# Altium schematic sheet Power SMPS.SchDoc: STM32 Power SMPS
size A3; Date: Not used; ApprovedBy: Not used; CheckedBy: Not used; Author: Not used; CompanyName: STMicroelectronics; DrawnBy: Not used; Engineer: Not used; Organization: Not used; Address1: Not used; Address2: Not used; Address3: Not used; Address4: Not used; DocumentNumber: 7; Revision: Not used; SheetNumber: 7; SheetTotal: 8
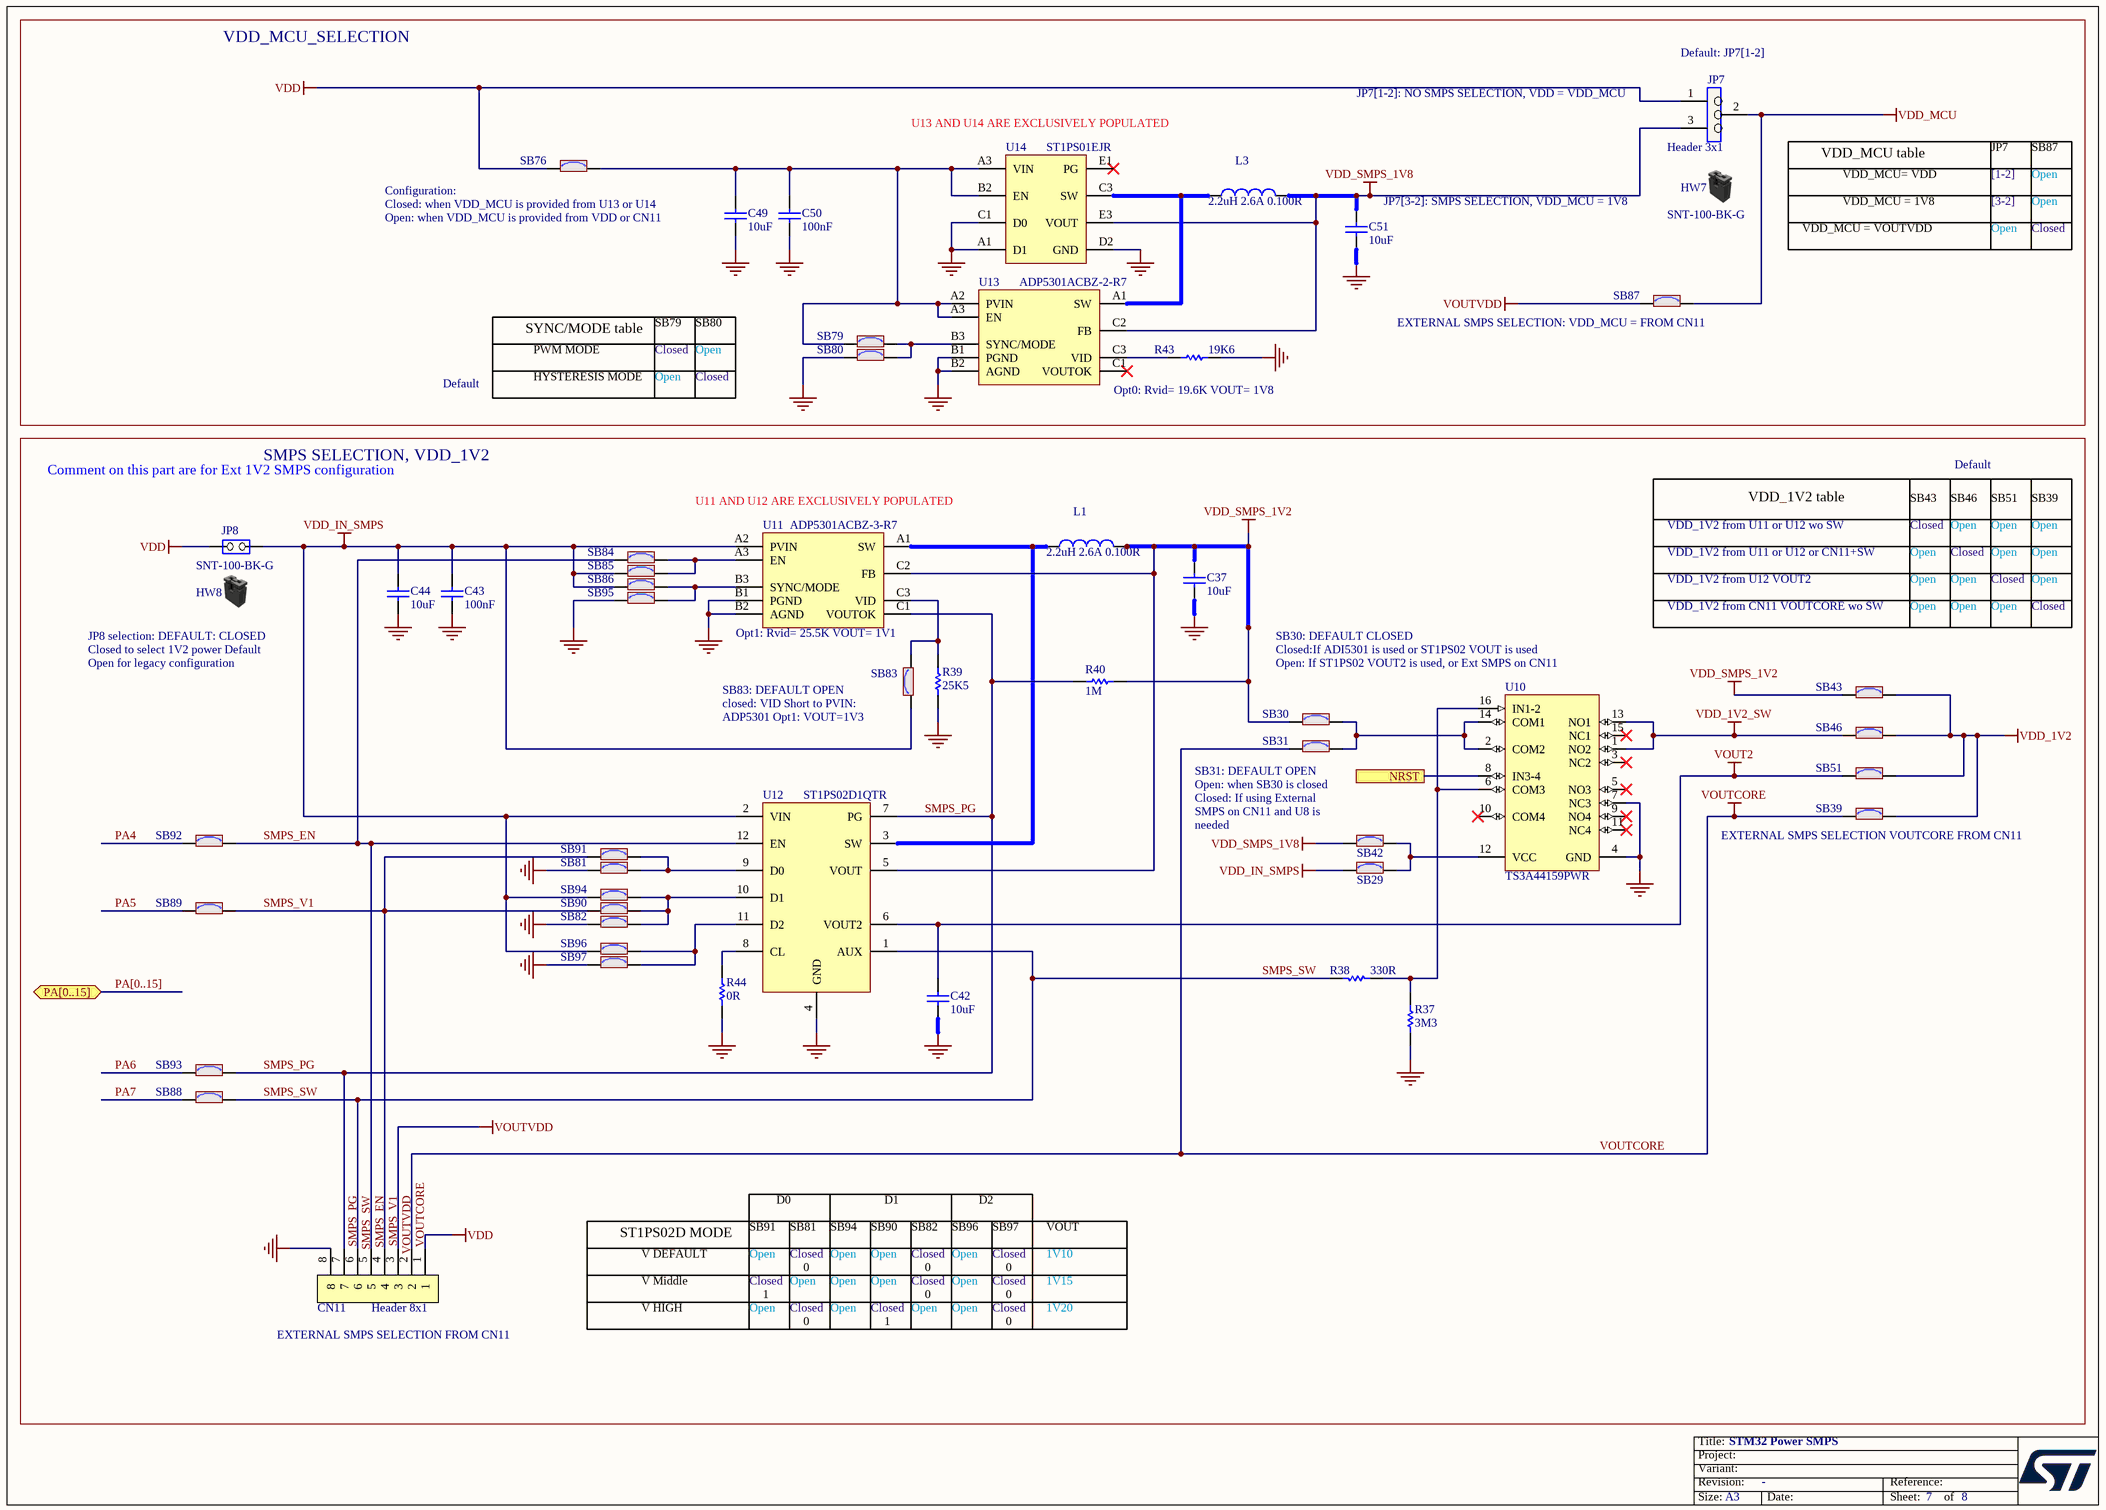
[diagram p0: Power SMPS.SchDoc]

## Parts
C37  value 10uF  [C0603]  (hidden comment: Capacitor)
C42  value 10uF  [C0603]  (hidden comment: Capacitor)
C43  value 100nF  [C0402]  (hidden comment: Capacitor)
C44  value 10uF  [C0603]  (hidden comment: Capacitor)
C49  value 10uF  [C0603]  (hidden comment: Capacitor)
C50  value 100nF  [C0603]  (hidden comment: Capacitor)
C51  value 10uF  [C0603]  (hidden comment: Capacitor)
CN11  Header 8x1  [CON_SAMTEC_TSW-108-07-X-S]
HW7  value SNT-100-BK-G  (hidden comment: Shunt Black 2.54mm)  (mechanical)
HW8  value SNT-100-BK-G  (hidden comment: Shunt Black 2.54mm)  (mechanical)
JP7  value Header 3x1  [CON_SAMTEC_TSW-103-07-F-S]  (hidden comment: Jumper_Header 3x1)
JP8  Jumper_Header 2x1  [CON_SAMTEC_TSW-102-07-G-S]  (value not drawn)
L1  value 2.2uH 2.6A 0.100R  [IND_TDK_VLS252010HBX-1]  (hidden comment: Inductor)
L3  value 2.2uH 2.6A 0.100R  [IND_TDK_VLS252010HBX-1]  (hidden comment: Inductor)
R37  value 3M3  [R0603]  (hidden comment: Resistor)
R38  value 330R  [R0603]  (hidden comment: Resistor)
R39  value 25K5  [R0603]  (hidden comment: Resistor)
R40  value 1M  [R0603]  (hidden comment: Resistor)
R43  value 19K6  [R0603]  (hidden comment: Resistor)
R44  value 0R  [R0603]  (hidden comment: Resistor)
SB29  SB_ON  [SOLDER-BRIDGE_R0603-0R]  (value not drawn)
SB30  SB_ON  [SOLDER-BRIDGE_R0603-0R]  (value not drawn)
SB31  SB_ON  [SOLDER-BRIDGE_R0603-0R]  (value not drawn)
SB39  SB_ON  [SOLDER-BRIDGE_R0603-0R]  (value not drawn)
SB42  SB_ON  [SOLDER-BRIDGE_R0603-0R]  (value not drawn)
SB43  SB_ON  [SOLDER-BRIDGE_R0603-0R]  (value not drawn)
SB46  SB_ON  [SOLDER-BRIDGE_R0603-0R]  (value not drawn)
SB51  SB_ON  [SOLDER-BRIDGE_R0603-0R]  (value not drawn)
SB76  SB_ON  [SOLDER-BRIDGE_R0603-0R]  (value not drawn)
SB79  SB_ON  [SOLDER-BRIDGE_R0603-0R]  (value not drawn)
SB80  SB_ON  [SOLDER-BRIDGE_R0603-0R]  (value not drawn)
SB81  SB_ON  [SOLDER-BRIDGE_R0603-0R]  (value not drawn)
SB82  SB_ON  [SOLDER-BRIDGE_R0603-0R]  (value not drawn)
SB83  SB_ON  [SOLDER-BRIDGE_R0603-0R]  (value not drawn)
SB84  SB_ON  [SOLDER-BRIDGE_R0603-0R]  (value not drawn)
SB85  SB_ON  [SOLDER-BRIDGE_R0603-0R]  (value not drawn)
SB86  SB_ON  [SOLDER-BRIDGE_R0603-0R]  (value not drawn)
SB87  SB_ON  [SOLDER-BRIDGE_R0603-0R]  (value not drawn)
SB88  SB_ON  [SOLDER-BRIDGE_R0603-0R]  (value not drawn)
SB89  SB_ON  [SOLDER-BRIDGE_R0603-0R]  (value not drawn)
SB90  SB_ON  [SOLDER-BRIDGE_R0603-0R]  (value not drawn)
SB91  SB_ON  [SOLDER-BRIDGE_R0603-0R]  (value not drawn)
SB92  SB_ON  [SOLDER-BRIDGE_R0603-0R]  (value not drawn)
SB93  SB_ON  [SOLDER-BRIDGE_R0603-0R]  (value not drawn)
SB94  SB_ON  [SOLDER-BRIDGE_R0603-0R]  (value not drawn)
SB95  SB_ON  [SOLDER-BRIDGE_R0603-0R]  (value not drawn)
SB96  SB_ON  [SOLDER-BRIDGE_R0603-0R]  (value not drawn)
SB97  SB_ON  [SOLDER-BRIDGE_R0603-0R]  (value not drawn)
U10  TS3A44159PWR  [ICC_TSSOP16_5P1X4P5_P065]
U11  value ADP5301ACBZ-3-R7  [ICC_WLCSP9_1P65X1P87_P050]  (hidden comment: ADP5301)
U12  ST1PS02D1QTR  [ICC_TQFN12_2X1P7_P040]
U13  value ADP5301ACBZ-2-R7  [ICC_WLCSP9_1P65X1P87_P050]  (hidden comment: ADP5301)
U14  ST1PS01EJR  [ICC_FLIP-CHIP-BGA8_1P11X1P41_P040]

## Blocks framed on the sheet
VDD_MCU_SELECTION: C49-C51 HW7 JP7 L3 R43 SB76 SB79 SB80 SB87 U13 U14
SMPS SELECTION, VDD_1V2: C37 C42-C44 CN11 HW8 JP8 L1 R37-R40 R44 SB29-SB31 SB39 SB42 SB43 SB46 SB51 SB81-SB86 SB88-SB97 U10-U12

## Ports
NRST, PA[0..15] (bidir)

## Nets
GND: C37.1 C42.1 C43.1 C44.1 C49.1 C50.1 C51.1 CN11.8 R37.1 R39.1 R43.2 R44.1 SB80.1 SB81.1 SB82.1 SB95.1 SB97.1 U10.4(GND) U10.7(NC3) U11.B1(PGND) U11.B2(AGND) U12.4(GND) U13.B1(PGND) U13.B2(AGND) U14.A1(D1) U14.C1(D0) U14.D2(GND)
VDD: CN11.1 JP7.1 JP8.1(COMMON) SB76.1
VDD_1V2: SB39.2 SB43.2 SB46.2 SB51.2
VDD_1V2_SW: SB46.1 U10.1(NO2) U10.13(NO1)
VDD_IN_SMPS: C43.2 C44.2 JP8.2(NO) SB29.1 SB83.1 SB85.1 SB86.1 SB94.1 SB96.1 U11.A2(PVIN) U12.2(VIN)
VDD_MCU: JP7.2 SB87.2
VDD_SMPS_1V2: C37.2 L1.2 R40.2 SB30.1 SB43.1 U11.C2(FB) U12.5(VOUT)
VDD_SMPS_1V8: C51.2 JP7.3 L3.2 SB42.1 U13.C2(FB) U14.E3(VOUT)
VOUT2: C42.2 SB51.1 U12.6(VOUT2)
VOUTCORE: CN11.2 SB31.1 SB39.1
VOUTVDD: CN11.3 SB87.1
NRST: U10.8(IN3-4) ; port NRST
PA4: SB92.2
PA5: SB89.2
PA6: SB93.2
PA7: SB88.2
SMPS_EN: CN11.5 SB84.1 SB92.1 U12.12(EN)
SMPS_PG: CN11.7 R40.1 SB93.1 U11.C1(VOUTOK) U12.7(PG)
SMPS_SW: CN11.6 R38.2 SB88.1 U12.1(AUX)
SMPS_V1: CN11.4 SB89.1 SB90.1 SB91.1
NetC49_2: C49.2 C50.2 SB76.2 SB79.1 U13.A2(PVIN) U13.A3(EN) U14.A3(VIN) U14.B2(EN)
NetL1_1: L1.1 U11.A1(SW) U12.3(SW)
NetL3_1: L3.1 U13.A1(SW) U14.C3(SW)
NetR37_2: R37.2 R38.1 U10.6(COM3) U10.16(IN1-2)
NetR39_2: R39.2 SB83.2 U11.C3(VID)
NetR43_1: R43.1 U13.C3(VID)
NetR44_2: R44.2 U12.8(CL)
NetSB29_2: SB29.2 SB42.2 U10.12(VCC)
NetSB30_2: SB30.2 SB31.2 U10.2(COM2) U10.14(COM1)
NetSB79_2: SB79.2 SB80.2 U13.B3(SYNC/MODE)
NetSB81_2: SB81.2 SB91.2 U12.9(D0)
NetSB82_2: SB82.2 SB90.2 SB94.2 U12.10(D1)
NetSB84_2: SB84.2 SB85.2 U11.A3(EN)
NetSB86_2: SB86.2 SB95.2 U11.B3(SYNC/MODE)
NetSB96_2: SB96.2 SB97.2 U12.11(D2)

Not connected (* = marked no-connect by the designer): U10 3(NC2)* 5(NO3)* 9(NO4)* 10(COM4)* 11(NC4)* 15(NC1)*; U13 C1(VOUTOK)*; U14 E1(PG)*

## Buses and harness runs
bus PA[0..15] = port PA[0..15]

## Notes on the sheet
- JP7[1-2]: NO SMPS SELECTION, VDD = VDD_MCU
- (near JP7) Default: JP7[1-2]
- (near U14) U13 AND U14 ARE EXCLUSIVELY POPULATED
- VDD_MCU table
- VDD_MCU= VDD
- JP7
- [1-2]
- SB87
- Open
- (near SB76) Configuration:
  Closed: when VDD_MCU is provided from U13 or U14
  Open: when VDD_MCU is provided from VDD or CN11
- (near C51) JP7[3-2]: SMPS SELECTION, VDD_MCU = 1V8
- VDD_MCU = VOUTVDD
- VDD_MCU = 1V8
- [3-2]
- Closed
- SYNC/MODE table
- PWM MODE
- HYSTERESIS MODE
- SB79
- SB80
- (near SB87) EXTERNAL SMPS SELECTION: VDD_MCU = FROM CN11
- Default
- Opt0: Rvid= 19.6K VOUT= 1V8
- Comment on this part are for Ext 1V2 SMPS configuration
- (near U11) U11 AND U12 ARE EXCLUSIVELY POPULATED
- VDD_1V2 table
- SB43
- SB46
- SB51
- SB39
- VDD_1V2 from U11 or U12 wo SW
- VDD_1V2 from U11 or U12 or CN11+SW
- VDD_1V2 from U12 VOUT2
- (near U11) Opt1: Rvid= 25.5K VOUT= 1V1
- VDD_1V2 from CN11 VOUTCORE wo SW
- JP8 selection: DEFAULT: CLOSED
  Closed to select 1V2 power Default
  Open for legacy configuration
- (near SB83) SB83: DEFAULT OPEN
  closed: VID Short to PVIN:
  ADP5301 Opt1: VOUT=1V3
- SB30: DEFAULT CLOSED
  Closed:If ADI5301 is used or ST1PS02 VOUT is used
  Open: If ST1PS02 VOUT2 is used, or Ext SMPS on CN11
- SB31: DEFAULT OPEN
  Open: when SB30 is closed
  Closed: If using External SMPS on CN11 and U8 is needed
- (near SB39) EXTERNAL SMPS SELECTION VOUTCORE FROM CN11
- ST1PS02D MODE
- V DEFAULT
- SB91
- D0
- SB81
- SB94
- SB90
- D1
- SB82
- SB96
- D2
- SB97
- VOUT
- 1V10
- V Middle
- V HIGH
- 1
- 0
- 1V15
- 1V20
- EXTERNAL SMPS SELECTION FROM CN11

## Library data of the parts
C37 C42 C44 C49 C51 = MCD-00243: Capacitor, MLCC, 10uF, 6V3, X5R, +/-10%, 0603, T=0,8mm; Manufacturer_Part_Number: CC0603KRX5R5BB106; Manufacturer: YAGEO; Part_Preference: Recommended
C43 = MCD-00006: Capacitor, MLCC, 100nF, 16V, X7R, +/-10%, 0402, T=0.5mm; Manufacturer_Part_Number: CC0402KRX7R7BB104; Manufacturer: YAGEO; Part_Preference: Recommended; Alternate_Manufacturer: MURATA; Alternate_Manufacturer_Part_Number: GCM155R71C104KA55D; Order_Code_RS: 616-9701
C50 = MCD-00237: Capacitor, MLCC, 100nF, 6V3, X5R, +/-10%, 0603, T=0.8mm; Part_Preference: Not recommended; Manufacturer: YAGEO; Manufacturer_Part_Number: CC0603KRX5R5BB104; Component_Country_Of_Origin: China; ShowFields: YES; ID: 2631
CN11 = MCD-00239: Header, 8x1, 2,54mm, VR, TH, Height 5.84mm/2.54mm; Manufacturer_Part_Number: TSW-108-07-G-S; Manufacturer: SAMTEC; Part_Type: Connector; Part_Preference: Recommended
HW7 HW8 = MCD-00043: SHUNT 2.54mm BLACK; Manufacturer: SAMTEC; Part_Type: Misc; Part_Preference: Recommended; Alternate_Manufacturer: JIUBABA; Alternate_Manufacturer_Part_Number: 316102S111A
JP7 = MCD-00111: Header, 3x1, 2,54mm, VR, TH, Height 5.84mm/2.54mm; Manufacturer_Part_Number: TSW-103-07-F-S; Manufacturer: SAMTEC; Part_Type: Connector; Part_Preference: Recommended; Alternate_Manufacturer: FCI; Alternate_Manufacturer_Part_Number: 77311-118-03LF
JP8 = MCD-00045: Header, 2x1, 2,54mm, VR, TH, Height 5.84mm/2.54mm; Manufacturer_Part_Number: TSW-102-07-G-S; Manufacturer: SAMTEC; Part_Type: Connector; Part_Preference: Recommended; Alternate_Manufacturer: JIUBABA; LIANYI; Alternate_Manufacturer_Part_Number: 313102S111116;313102S111116; Value: Shunt not fitted
L1 L3 = MCD-00240: FIXED IND 2.2UH 2.6A 100 mOHM 20% SMD; Manufacturer_Part_Number: VLS252010HBX-2R2M-1; Manufacturer: TDK; Part_Preference: Recommended
R37 = MCD-00241: Resistor,3M3,0603,1%,1/10W; Manufacturer_Part_Number: RC0603FR-073M3L; Manufacturer: YAGEO; BMS_Part_Number: 9129788; Part_Preference: Recommended; Order_Code_RS: 504-6540
R38 = MCD-00197: Resistor,330R,0603,1%,1/10W; Manufacturer_Part_Number: RC0603FR-07330RL; Manufacturer: YAGEO; BMS_Part_Number: 9129729; Part_Preference: Recommended
R39 = MCD-00546: Resistor,25K5,0603,1%,1/10W; Manufacturer_Part_Number: RC0603FR-0725K5L; Manufacturer: YAGEO; Part_Preference: Recommended
R40 = MCD-00257: Resistor,1M,0603,1%,1/10W; Manufacturer_Part_Number: RC0603FR-071ML; Manufacturer: YAGEO; Part_Preference: Recommended
R43 = MCD-00242: Resistor,19K6,0603,1%,1/10W; Manufacturer_Part_Number: RC0603FR-0719K6L; Manufacturer: YAGEO; Part_Preference: Recommended
R44 = MCD-00056: Resistor,0R,0603,5%,1/10W; Manufacturer_Part_Number: RC0603JR-070RL; Manufacturer: YAGEO; Part_Preference: Recommended
SB29-SB31 SB39 SB42 SB43 SB46 SB51 SB76 SB79-SB97 = MCD-00071: Solder Bridge ON; Part_Type: Misc; Part_Preference: Recommended; Manufacturer: YAGEO; Manufacturer_Part_Number: RC0603JR-070RL
U10 = MCD-00090: SPDT analog switch 4-Channel 2:1 bidirectional; Manufacturer: TEXAS INSTRUMENTS; Part_Type: IC; Part_Preference: Recommended
U11 = MCD-00230: UL Step down regulator: Opt1; Part_Type: IC; Manufacturer: ANALOG DEVICES; Part_Preference: Recommended
U12 = MCD-00229: 400mA Nano-Quiescent Step down converter with Aux switch; Manufacturer: STMICROELECTRONICS; Part_Type: IC; BMS_Part_Number: 9176335; Part_Preference: Recommended; Manufacturer_HQ_COO: EU
U13 = MCD-00226: UL Step down regulator: Opt0; Manufacturer: ANALOG DEVICES; Part_Type: IC; Part_Preference: Recommended
U14 = MCD-00228: 400mA Nano-Quiescent Step down converter; Manufacturer: STMICROELECTRONICS; Part_Type: IC; BMS_Part_Number: 9176329; Part_Preference: Recommended; Manufacturer_HQ_COO: EU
